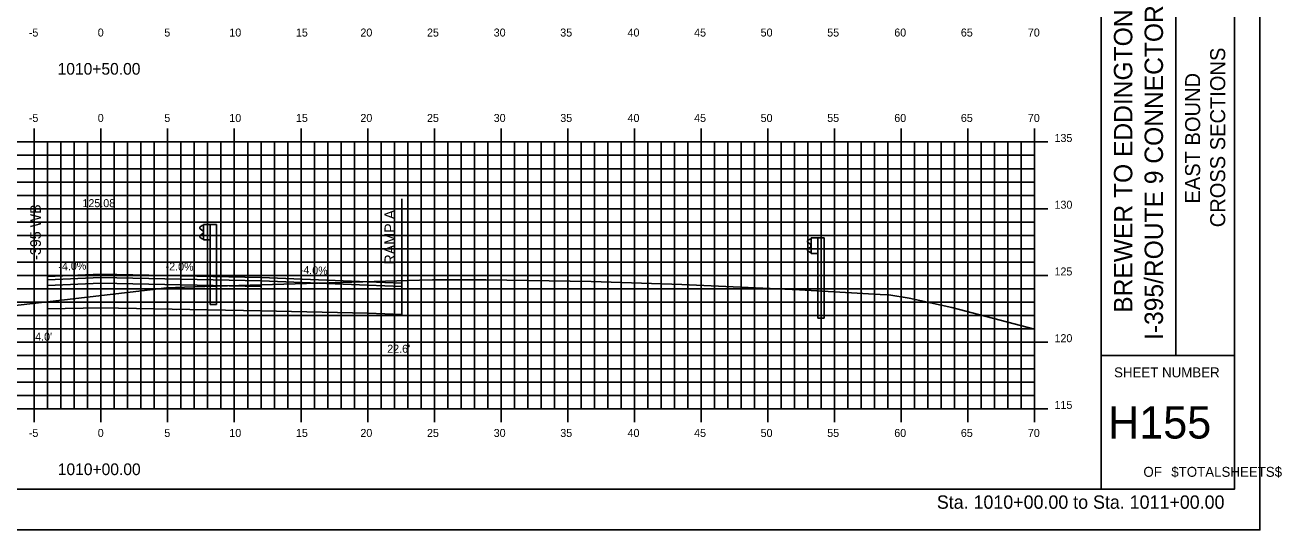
# Model space of a CAD drawing. Extents: x 852182 to 852354, y 365624 to 365734.
# Drawn here: x 852259.3 to 852353.6, y 365624 to 365661.8 of the extents above; entities that cross this region are included whole.
import ezdxf

# ---------------------------------------------------------------- set-up
doc = ezdxf.new("R2010")
doc.units = 0
for name, color, linetype in [('ANNOTATION', 7, 'Continuous'), ('BORDER', 7, 'Continuous'), ('D_Roadway_Centerline', 7, 'Continuous'), ('D_Roadway_Centerline_Text', 7, 'Continuous'), ('D_Roadway_Edge_Shoulder', 7, 'Continuous'), ('D_Roadway_Edge_TW', 7, 'Continuous'), ('D_Roadway_FinishedGrade', 7, 'Continuous'), ('D_Roadway_Pavement', 7, 'Continuous'), ('D_Roadway_SubGrade', 7, 'Continuous'), ('D_Text_Standard', 7, 'Continuous'), ('Default', 7, 'Continuous'), ('H_V ANNOTATION', 7, 'Continuous'), ('M_Guardrail', 7, 'Continuous'), ('M_Roadway_Centerline', 7, 'Continuous'), ('MAJOR', 7, 'Continuous'), ('MINOR', 7, 'Continuous'), ('PLOT BOUNDARY', 7, 'Continuous'), ('S_Roadway_Centerline', 7, 'Continuous')]:
    doc.layers.add(name, color=color, linetype=linetype)

msp = doc.modelspace()

# ---------------------------------------------------------------- linework, layer by layer
at = {"layer": 'BORDER'}
for p, q in [((852340.035, 365627.027), (852340.035, 365732.027)), ((852345.627, 365637.03), (852345.627, 365672.03)), ((852340.035, 365637.03), (852350.035, 365637.03))]:
    msp.add_line(p, q, dxfattribs=at)
msp.add_lwpolyline([(852190.035, 365627.027), (852350.035, 365627.027), (852350.035, 365732.027), (852190.035, 365732.027)], close=True, dxfattribs=at)
at = {"layer": 'D_Roadway_Centerline'}
for p, q in [((852285.035, 365642.552), (852287.602, 365642.449)), ((852285.035, 365642.302), (852287.602, 365642.199))]:
    msp.add_line(p, q, dxfattribs=at)
for points in [[(852261.033, 365642.952), (852261.035, 365642.952), (852265.034, 365643.112), (852265.035, 365643.112), (852277.031, 365642.872), (852277.035, 365642.872), (852285.034, 365642.552), (852285.035, 365642.552)], [(852285.035, 365640.212), (852287.603, 365640.098), (852287.603, 365642.262)]]:
    msp.add_lwpolyline(points, dxfattribs=at)
at = {"layer": 'D_Roadway_Edge_Shoulder'}
for points in [[(852265.035, 365643.112), (852261.035, 365642.952), (852261.035, 365642.702), (852265.035, 365642.862)], [(852277.035, 365642.872), (852285.035, 365642.552), (852285.035, 365642.302), (852277.035, 365642.622)]]:
    msp.add_lwpolyline(points, close=True, dxfattribs=at)
at = {"layer": 'D_Roadway_Edge_TW'}
msp.add_lwpolyline([(852265.035, 365643.112), (852277.035, 365642.872), (852277.035, 365642.622), (852265.035, 365642.862)], close=True, dxfattribs=at)
msp.add_lwpolyline([(852277.035, 365642.872), (852277.035, 365642.705)], dxfattribs=at)
at = {"layer": 'D_Roadway_FinishedGrade'}
for p, q in [((852261.035, 365642.952), (852261.035, 365642.702)), ((852277.035, 365642.872), (852277.035, 365642.622))]:
    msp.add_line(p, q, dxfattribs=at)
for points in [[(852265.035, 365643.112), (852265.035, 365642.862), (852261.035, 365642.702)], [(852285.035, 365642.552), (852285.035, 365642.302), (852277.035, 365642.622)]]:
    msp.add_lwpolyline(points, dxfattribs=at)
at = {"layer": 'D_Roadway_Pavement'}
for points in [[(852265.035, 365642.862), (852261.035, 365642.702), (852261.035, 365642.285), (852265.035, 365642.445)], [(852265.035, 365642.862), (852277.035, 365642.622), (852277.035, 365642.205), (852265.035, 365642.445)]]:
    msp.add_lwpolyline(points, close=True, dxfattribs=at)
msp.add_lwpolyline([(852277.035, 365642.705), (852277.035, 365642.205)], dxfattribs=at)
msp.add_lwpolyline([(852277.035, 365642.705), (852277.035, 365642.205)], dxfattribs=at)
at = {"layer": 'D_Roadway_SubGrade'}
for p, q in [((852261.035, 365648.856), (852261.035, 365640.532)), ((852287.602, 365648.758), (852287.602, 365640.098))]:
    msp.add_line(p, q, dxfattribs=at)
for points in [[(852265.035, 365642.445), (852261.035, 365642.285), (852261.035, 365642.785), (852261.035, 365642.952), (852261.035, 365640.532), (852265.035, 365640.612)], [(852265.035, 365642.445), (852277.035, 365642.205), (852277.035, 365640.372), (852265.035, 365640.612)], [(852277.035, 365642.205), (852277.035, 365642.622), (852285.035, 365642.302), (852285.035, 365642.552), (852285.035, 365640.212), (852277.035, 365640.372)]]:
    msp.add_lwpolyline(points, close=True, dxfattribs=at)
msp.add_lwpolyline([(852277.035, 365642.205), (852277.035, 365640.372)], dxfattribs=at)
at = {"layer": 'Default'}
for p in [(852287.603, 365642.262), (852285.035, 365640.212)]:
    msp.add_line(p, (852287.603, 365640.098), dxfattribs=at)
at = {"layer": 'M_Guardrail'}
for p, q in [((852272.628, 365646.76), (852272.485, 365646.66)), ((852272.485, 365646.517), (852272.68, 365646.381)), ((852272.727, 365646.781), (852272.645, 365646.767)), ((852272.727, 365646.854), (852273.217, 365646.854)), ((852272.727, 365645.687), (852272.727, 365646.854)), ((852273.217, 365646.854), (852273.708, 365646.854)), ((852273.217, 365646.854), (852273.217, 365645.687)), ((852273.708, 365646.854), (852273.708, 365640.854)), ((852272.68, 365646.161), (852272.485, 365646.025)), ((852272.485, 365645.881), (852272.628, 365645.781)), ((852272.645, 365645.775), (852272.727, 365645.76)), ((852272.714, 365646.316), (852272.714, 365646.225)), ((852273.217, 365645.687), (852272.727, 365645.687)), ((852273.217, 365640.854), (852273.217, 365645.687)), ((852318.189, 365645.744), (852318.046, 365645.644)), ((852318.046, 365645.501), (852318.241, 365645.365)), ((852318.288, 365645.765), (852318.206, 365645.751)), ((852318.288, 365645.838), (852318.778, 365645.838)), ((852318.288, 365644.672), (852318.288, 365645.838)), ((852318.778, 365645.838), (852319.269, 365645.838)), ((852318.778, 365645.838), (852318.778, 365644.672)), ((852319.269, 365645.838), (852319.269, 365639.838)), ((852318.241, 365645.145), (852318.046, 365645.009)), ((852318.046, 365644.866), (852318.189, 365644.766)), ((852318.206, 365644.759), (852318.288, 365644.745)), ((852318.275, 365645.301), (852318.275, 365645.21)), ((852318.778, 365644.672), (852318.288, 365644.672)), ((852318.778, 365639.838), (852318.778, 365644.672)), ((852273.217, 365640.854), (852273.708, 365640.854)), ((852318.778, 365639.838), (852319.269, 365639.838))]:
    msp.add_line(p, q, dxfattribs=at)
for centre, major_axis, start_param, end_param in [((852272.535, 365646.588), (-0.0877, 0), 5.323254, 7.243116), ((852272.652, 365646.726), (-0.0417, 0), 4.886922, 5.323254), ((852272.535, 365645.953), (-0.0877, 0), 5.323254, 7.243116), ((852272.652, 365645.815), (-0.0417, 0), 0.959931, 1.396263), ((852272.635, 365646.316), (0.0789, 0), 0, 0.959931), ((852272.635, 365646.225), (0.0789, 0), 5.323254, 6.283185), ((852318.096, 365645.573), (-0.0877, 0), 5.323254, 7.243116), ((852318.213, 365645.71), (-0.0417, 0), 4.886922, 5.323254), ((852318.096, 365644.937), (-0.0877, 0), 5.323254, 7.243116), ((852318.213, 365644.8), (-0.0417, 0), 0.959931, 1.396263), ((852318.196, 365645.301), (0.0789, 0), 0, 0.959931), ((852318.196, 365645.21), (0.0789, 0), 5.323254, 6.283185)]:
    msp.add_ellipse(centre, major_axis=major_axis, ratio=0.995501, start_param=start_param, end_param=end_param, dxfattribs=at)
at = {"layer": 'MAJOR'}
for p, q in [((852260.035, 365654.029), (852260.035, 365653.027)), ((852265.035, 365654.029), (852265.035, 365653.027)), ((852270.035, 365654.029), (852270.035, 365653.027)), ((852275.035, 365654.029), (852275.035, 365653.027)), ((852280.035, 365654.029), (852280.035, 365653.027)), ((852285.035, 365654.029), (852285.035, 365653.027)), ((852290.035, 365654.029), (852290.035, 365653.027)), ((852295.035, 365654.029), (852295.035, 365653.027)), ((852300.035, 365654.029), (852300.035, 365653.027)), ((852305.035, 365654.029), (852305.035, 365653.027)), ((852310.035, 365654.029), (852310.035, 365653.027)), ((852315.035, 365654.029), (852315.035, 365653.027)), ((852320.035, 365654.029), (852320.035, 365653.027)), ((852325.035, 365654.029), (852325.035, 365653.027)), ((852330.035, 365654.029), (852330.035, 365653.027)), ((852335.035, 365654.029), (852335.035, 365653.027)), ((852195.035, 365653.027), (852335.035, 365653.027)), ((852195.035, 365653.027), (852335.035, 365653.027)), ((852260.035, 365633.027), (852260.035, 365653.027)), ((852265.035, 365633.027), (852265.035, 365653.027)), ((852270.035, 365633.027), (852270.035, 365653.027)), ((852275.035, 365633.027), (852275.035, 365653.027)), ((852280.035, 365633.027), (852280.035, 365653.027)), ((852285.035, 365633.027), (852285.035, 365653.027)), ((852290.035, 365633.027), (852290.035, 365653.027)), ((852295.035, 365633.027), (852295.035, 365653.027)), ((852300.035, 365633.027), (852300.035, 365653.027)), ((852305.035, 365633.027), (852305.035, 365653.027)), ((852310.035, 365633.027), (852310.035, 365653.027)), ((852315.035, 365633.027), (852315.035, 365653.027)), ((852320.035, 365633.027), (852320.035, 365653.027)), ((852325.035, 365633.027), (852325.035, 365653.027)), ((852330.035, 365633.027), (852330.035, 365653.027)), ((852336.037, 365653.027), (852334.033, 365653.027)), ((852335.035, 365633.027), (852335.035, 365653.027)), ((852335.035, 365633.027), (852335.035, 365653.027)), ((852195.035, 365648.027), (852335.035, 365648.027)), ((852336.037, 365648.027), (852334.033, 365648.027)), ((852195.035, 365643.027), (852335.035, 365643.027)), ((852336.037, 365643.027), (852334.033, 365643.027)), ((852195.035, 365638.027), (852335.035, 365638.027)), ((852336.037, 365638.027), (852334.033, 365638.027)), ((852195.035, 365633.027), (852335.035, 365633.027)), ((852195.035, 365633.027), (852335.035, 365633.027)), ((852260.035, 365632.025), (852260.035, 365633.027)), ((852265.035, 365632.025), (852265.035, 365633.027)), ((852270.035, 365632.025), (852270.035, 365633.027)), ((852275.035, 365632.025), (852275.035, 365633.027)), ((852280.035, 365632.025), (852280.035, 365633.027)), ((852285.035, 365632.025), (852285.035, 365633.027)), ((852290.035, 365632.025), (852290.035, 365633.027)), ((852295.035, 365632.025), (852295.035, 365633.027)), ((852300.035, 365632.025), (852300.035, 365633.027)), ((852305.035, 365632.025), (852305.035, 365633.027)), ((852310.035, 365632.025), (852310.035, 365633.027)), ((852315.035, 365632.025), (852315.035, 365633.027)), ((852320.035, 365632.025), (852320.035, 365633.027)), ((852325.035, 365632.025), (852325.035, 365633.027)), ((852330.035, 365632.025), (852330.035, 365633.027)), ((852336.037, 365633.027), (852334.033, 365633.027)), ((852335.035, 365632.025), (852335.035, 365633.027))]:
    msp.add_line(p, q, dxfattribs=at)
at = {"layer": 'MINOR'}
for p, q in [((852261.035, 365633.027), (852261.035, 365653.027)), ((852262.035, 365633.027), (852262.035, 365653.027)), ((852263.035, 365633.027), (852263.035, 365653.027)), ((852264.035, 365633.027), (852264.035, 365653.027)), ((852266.035, 365633.027), (852266.035, 365653.027)), ((852267.035, 365633.027), (852267.035, 365653.027)), ((852268.035, 365633.027), (852268.035, 365653.027)), ((852269.035, 365633.027), (852269.035, 365653.027)), ((852271.035, 365633.027), (852271.035, 365653.027)), ((852272.035, 365633.027), (852272.035, 365653.027)), ((852273.035, 365633.027), (852273.035, 365653.027)), ((852274.035, 365633.027), (852274.035, 365653.027)), ((852276.035, 365633.027), (852276.035, 365653.027)), ((852277.035, 365633.027), (852277.035, 365653.027)), ((852278.035, 365633.027), (852278.035, 365653.027)), ((852279.035, 365633.027), (852279.035, 365653.027)), ((852281.035, 365633.027), (852281.035, 365653.027)), ((852282.035, 365633.027), (852282.035, 365653.027)), ((852283.035, 365633.027), (852283.035, 365653.027)), ((852284.035, 365633.027), (852284.035, 365653.027)), ((852286.035, 365633.027), (852286.035, 365653.027)), ((852287.035, 365633.027), (852287.035, 365653.027)), ((852288.035, 365633.027), (852288.035, 365653.027)), ((852289.035, 365633.027), (852289.035, 365653.027)), ((852291.035, 365633.027), (852291.035, 365653.027)), ((852292.035, 365633.027), (852292.035, 365653.027)), ((852293.035, 365633.027), (852293.035, 365653.027)), ((852294.035, 365633.027), (852294.035, 365653.027)), ((852296.035, 365633.027), (852296.035, 365653.027)), ((852297.035, 365633.027), (852297.035, 365653.027)), ((852298.035, 365633.027), (852298.035, 365653.027)), ((852299.035, 365633.027), (852299.035, 365653.027)), ((852301.035, 365633.027), (852301.035, 365653.027)), ((852302.035, 365633.027), (852302.035, 365653.027)), ((852303.035, 365633.027), (852303.035, 365653.027)), ((852304.035, 365633.027), (852304.035, 365653.027)), ((852306.035, 365633.027), (852306.035, 365653.027)), ((852307.035, 365633.027), (852307.035, 365653.027)), ((852308.035, 365633.027), (852308.035, 365653.027)), ((852309.035, 365633.027), (852309.035, 365653.027)), ((852311.035, 365633.027), (852311.035, 365653.027)), ((852312.035, 365633.027), (852312.035, 365653.027)), ((852313.035, 365633.027), (852313.035, 365653.027)), ((852314.035, 365633.027), (852314.035, 365653.027)), ((852316.035, 365633.027), (852316.035, 365653.027)), ((852317.035, 365633.027), (852317.035, 365653.027)), ((852318.035, 365633.027), (852318.035, 365653.027)), ((852319.035, 365633.027), (852319.035, 365653.027)), ((852321.035, 365633.027), (852321.035, 365653.027)), ((852322.035, 365633.027), (852322.035, 365653.027)), ((852323.035, 365633.027), (852323.035, 365653.027)), ((852324.035, 365633.027), (852324.035, 365653.027)), ((852326.035, 365633.027), (852326.035, 365653.027)), ((852327.035, 365633.027), (852327.035, 365653.027)), ((852328.035, 365633.027), (852328.035, 365653.027)), ((852329.035, 365633.027), (852329.035, 365653.027)), ((852331.035, 365633.027), (852331.035, 365653.027)), ((852332.035, 365633.027), (852332.035, 365653.027)), ((852333.035, 365633.027), (852333.035, 365653.027)), ((852334.035, 365633.027), (852334.035, 365653.027)), ((852195.035, 365652.027), (852335.035, 365652.027)), ((852335.035, 365652.027), (852334.033, 365652.027)), ((852195.035, 365651.027), (852335.035, 365651.027)), ((852335.035, 365651.027), (852334.033, 365651.027)), ((852195.035, 365650.027), (852335.035, 365650.027)), ((852335.035, 365650.027), (852334.033, 365650.027)), ((852195.035, 365649.027), (852335.035, 365649.027)), ((852335.035, 365649.027), (852334.033, 365649.027)), ((852195.035, 365647.027), (852335.035, 365647.027)), ((852335.035, 365647.027), (852334.033, 365647.027)), ((852195.035, 365646.027), (852335.035, 365646.027)), ((852335.035, 365646.027), (852334.033, 365646.027)), ((852195.035, 365645.027), (852335.035, 365645.027)), ((852335.035, 365645.027), (852334.033, 365645.027)), ((852195.035, 365644.027), (852335.035, 365644.027)), ((852335.035, 365644.027), (852334.033, 365644.027)), ((852195.035, 365642.027), (852335.035, 365642.027)), ((852335.035, 365642.027), (852334.033, 365642.027)), ((852195.035, 365641.027), (852335.035, 365641.027)), ((852335.035, 365641.027), (852334.033, 365641.027)), ((852195.035, 365640.027), (852335.035, 365640.027)), ((852335.035, 365640.027), (852334.033, 365640.027)), ((852195.035, 365639.027), (852335.035, 365639.027)), ((852335.035, 365639.027), (852334.033, 365639.027)), ((852195.035, 365637.027), (852335.035, 365637.027)), ((852335.035, 365637.027), (852334.033, 365637.027)), ((852195.035, 365636.027), (852335.035, 365636.027)), ((852335.035, 365636.027), (852334.033, 365636.027)), ((852195.035, 365635.027), (852335.035, 365635.027)), ((852335.035, 365635.027), (852334.033, 365635.027)), ((852195.035, 365634.027), (852335.035, 365634.027)), ((852335.035, 365634.027), (852334.033, 365634.027))]:
    msp.add_line(p, q, dxfattribs=at)
at = {"layer": 'PLOT BOUNDARY'}
msp.add_lwpolyline([(852181.942, 365623.968), (852351.942, 365623.968), (852351.942, 365733.968), (852181.942, 365733.968)], close=True, dxfattribs=at)
at = {"layer": 'S_Roadway_Centerline'}
msp.add_lwpolyline([(852253.547, 365640.203), (852260.793, 365641.02), (852268.733, 365641.948), (852269.959, 365642.112), (852271.961, 365642.187), (852288.922, 365642.682), (852289.897, 365642.696), (852291.683, 365642.711), (852293.902, 365642.695), (852301.783, 365642.586), (852308.58, 365642.355), (852317.409, 365641.953), (852323.456, 365641.603), (852324.121, 365641.57), (852325.632, 365641.33), (852328.842, 365640.62), (852335.035, 365639.001)], dxfattribs=at)

# ---------------------------------------------------------------- texts
at = {"layer": 'ANNOTATION'}
for s, height, rotation, p in [('I-395 WB', 0.8, 90, (852260.528, 365643.897)), ('RAMP A', 0.8, 90, (852287.095, 365643.842)), ('-4.0%', 0.6, 2.29041, (852261.85, 365643.385)), ('-2.0%', 0.6, 358.85423, (852269.876, 365643.415)), ('-4.0%', 0.6, 357.7093, (852279.93, 365643.157))]:
    msp.add_text(s, height=height, rotation=rotation, dxfattribs=at).set_placement(p)
at = {"layer": 'BORDER'}
for s, height, p in [('BREWER TO EDDINGTON', 1.37787, (852342.369, 365640.231)), ('I-395/ROUTE 9 CONNECTOR', 1.37787, (852344.67, 365638.192)), ('CROSS SECTIONS', 1.125, (852349.333, 365646.638)), ('EAST BOUND', 1.125, (852347.454, 365648.418))]:
    msp.add_text(s, height=height, rotation=90, dxfattribs=at).set_placement(p)
for s, height, p in [('SHEET NUMBER', 0.74527, (852341.001, 365635.393)), ('H155', 2.4194, (852340.551, 365630.809)), ('OF', 0.7453, (852343.202, 365627.94)), ('$TOTALSHEETS$', 0.74527, (852345.292, 365627.94))]:
    msp.add_text(s, height=height, dxfattribs=at).set_placement(p)
at = {"layer": 'D_Roadway_Centerline'}
for s, p in [('C', (852265.03, 365643.112)), ('L', (852265.035, 365643.104))]:
    msp.add_text(s, height=0.0146, dxfattribs=at).set_placement(p)
at = {"layer": 'D_Roadway_Centerline_Text'}
msp.add_text('125.08', height=0.6, dxfattribs=at).set_placement((852263.647, 365648.144))
at = {"layer": 'D_Text_Standard'}
for s, p in [("4.0'", (852260.101, 365638.14)), ("22.6'", (852286.503, 365637.235))]:
    msp.add_text(s, height=0.6, dxfattribs=at).set_placement(p)
at = {"layer": 'H_V ANNOTATION'}
for s, height, p in [('-5', 0.6, (852259.626, 365660.927)), ('0', 0.6, (852264.794, 365660.927)), ('5', 0.6, (852269.786, 365660.927)), ('10', 0.6, (852274.661, 365660.927)), ('15', 0.6, (852279.653, 365660.927)), ('20', 0.6, (852284.489, 365660.927)), ('25', 0.6, (852289.481, 365660.927)), ('30', 0.6, (852294.484, 365660.927)), ('35', 0.6, (852299.476, 365660.927)), ('40', 0.6, (852304.521, 365660.927)), ('45', 0.6, (852309.513, 365660.927)), ('50', 0.6, (852314.5, 365660.927)), ('55', 0.6, (852319.492, 365660.927)), ('60', 0.6, (852324.521, 365660.927)), ('65', 0.6, (852329.513, 365660.927)), ('70', 0.6, (852334.537, 365660.927)), ('1010+50.00', 0.875, (852261.782, 365658.07)), ('-5', 0.6, (852259.626, 365654.527)), ('0', 0.6, (852264.794, 365654.527)), ('5', 0.6, (852269.786, 365654.527)), ('10', 0.6, (852274.661, 365654.527)), ('15', 0.6, (852279.653, 365654.527)), ('20', 0.6, (852284.489, 365654.527)), ('25', 0.6, (852289.481, 365654.527)), ('30', 0.6, (852294.484, 365654.527)), ('35', 0.6, (852299.476, 365654.527)), ('40', 0.6, (852304.521, 365654.527)), ('45', 0.6, (852309.513, 365654.527)), ('50', 0.6, (852314.5, 365654.527)), ('55', 0.6, (852319.492, 365654.527)), ('60', 0.6, (852324.521, 365654.527)), ('65', 0.6, (852329.513, 365654.527)), ('70', 0.6, (852334.537, 365654.527)), ('135', 0.6, (852336.535, 365653.027)), ('130', 0.6, (852336.535, 365648.027)), ('125', 0.6, (852336.535, 365643.027)), ('120', 0.6, (852336.535, 365638.027)), ('115', 0.6, (852336.535, 365633.027)), ('-5', 0.6, (852259.626, 365630.927)), ('0', 0.6, (852264.794, 365630.927)), ('5', 0.6, (852269.786, 365630.927)), ('10', 0.6, (852274.661, 365630.927)), ('15', 0.6, (852279.653, 365630.927)), ('20', 0.6, (852284.489, 365630.927)), ('25', 0.6, (852289.481, 365630.927)), ('30', 0.6, (852294.484, 365630.927)), ('35', 0.6, (852299.476, 365630.927)), ('40', 0.6, (852304.521, 365630.927)), ('45', 0.6, (852309.513, 365630.927)), ('50', 0.6, (852314.5, 365630.927)), ('55', 0.6, (852319.492, 365630.927)), ('60', 0.6, (852324.521, 365630.927)), ('65', 0.6, (852329.513, 365630.927)), ('70', 0.6, (852334.537, 365630.927)), ('1010+00.00', 0.875, (852261.797, 365628.07)), ('Sta. 1010+00.00 to Sta. 1011+00.00', 1.0002, (852327.712, 365625.547))]:
    msp.add_text(s, height=height, dxfattribs=at).set_placement(p)
at = {"layer": 'M_Roadway_Centerline'}
for s, p in [('C', (852291.678, 365642.711)), ('L', (852291.683, 365642.704))]:
    msp.add_text(s, height=0.0146, dxfattribs=at).set_placement(p)

doc.saveas('drawing.dxf')
